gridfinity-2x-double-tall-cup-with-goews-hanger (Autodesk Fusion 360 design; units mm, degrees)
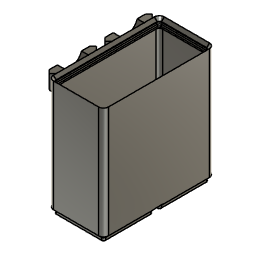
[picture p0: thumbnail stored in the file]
parameter "slotDimension" = 42
parameter "nestingDepth" = 5
parameter "nestingRimWidth" = 2.4
parameter "nestingClearance" = 0.25
parameter "cornerFillet" = 4
parameter "ledStripWidth" = 13
parameter "ledSlotHeight" = 4
parameter "screwTightDiameter" = 3
parameter "magnetDiameter" = 6.5
parameter "magnetThiccness" = 2.4
parameter "wallThiccness" = 1.2
sketch "Sketch1"
  line L1 (42, 42) -> (0, 42)
  line L2 (42, 0) -> (42, 42)
  line L3 (0, 0) -> (42, 0)
  line L4 (0, 42) -> (0, 0)
  line L5 (42, 0) -> (0, 42)
  line L6 (0, 21) -> (42, 21)
  line L7 (0, 14.5) -> (42, 14.5)
  line L8 (0, 27.5) -> (42, 27.5)
  line L9 (27.5, 0) -> (27.5, 42)
  line L10 (14.5, 0) -> (14.5, 42)
  line L11 (0, 0) -> (14.5, 14.5)
  circle C1 centre (8, 8) radius 1.5
  circle C2 centre (34, 8) radius 1.5
  circle C3 centre (34, 34) radius 1.5
  circle C4 centre (8, 34) radius 1.5
  circle C5 centre (8, 8) radius 3.25
  circle C6 centre (34, 8) radius 3.25
  circle C7 centre (34, 34) radius 3.25
  circle C8 centre (8, 34) radius 3.25
  point P1 (0, 0)
  point P6 (0, 0)
  point P5 (0, 0)
  point P7 (42, 21)
  point P8 (0, 21)
  point P9 (42, 14.5)
  point P10 (0, 14.5)
  point P11 (42, 27.5)
  point P12 (0, 27.5)
  point P13 (21, 21)
  point P18 (14.5, 14.5)
  point P19 (0, 0)
  point P20 (8, 8)
  point P4 (42, 0)
  point P3 (42, 42)
  point P24 (8, 8)
  horizontal L1
  perpendicular L1 L2
  parallel L1 L3
  parallel L2 L4
  coincident P1 P6
  coincident P1 P5
  midpoint L2 P7
  midpoint L4 P8
  coincident L2 P9
  coincident L4 P10
  perpendicular L4 L7
  symmetric L6 P9 P11
  symmetric L6 P10 P12
  midpoint L5 P13
  coincident L10 P18
  coincident L7 P18
  coincident P6 P19
  concentric C1 C5
  coincident L11 P20
  dimension "d1" distance P4 P5 = 42 (= "slotDimension")
  dimension "d2" distance P3 P4 = 42 (= "slotDimension")
  dimension "d65" distance L7 L8 = 13 (= "ledStripWidth")
  dimension "d69" diameter C1 = 3 (= "screwTightDiameter")
  dimension "d80" diameter C5 = 6.5 (= "magnetDiameter")
  dimension "d85" distance L3 P24 = 8
  dimension "d67" value = 90 (= "C-Pattern1-Angle")
  dimension "d71" value = 360 (= "C-Pattern2-Angle")
extrude "Extrude1" new body sketch "Sketch1" profile of L1 L2 L3 L4 blind 5 (= "nestingDepth")
work_plane "WorkPlane1" AlongDistance -21 (= "-slotDimension / 2")
sketch "Sketch2" plane through (0, 21, 0) normal (0, -1, 0) x axis (1, 0, 0)
  line L1 (0, 0) -> (42, 0)
  line L2 (0, 5) -> (0, 0)
  line L3 (2.4, 0.8) -> (3.2, 0)
  line L4 (0, 0) -> (3.2, 0)
  line L5 (2.4, 2.6) -> (2.4, 0.8)
  line L6 (0, 5) -> (2.4, 2.6)
  line L7 (-5.1222, 5) -> (0, 5)
  line L8 (-5.1222, -0.0937) -> (-5.1222, 5)
  line L9 (0, 0) -> (-5.1222, -0.0937)
  point P5 (3.2, 0)
  point P8 (0, 5)
  point P3 (0, 0)
  point P9 (0, 0)
  point P4 (0, 5)
  point P10 (0, 5)
  point P13 (0, 0)
  point P6 (2.4, 0.8)
  point P1 (0, 0)
  horizontal L4
  coincident L1 P5
  perpendicular L1 L5
  coincident L2 P8
  coincident P3 P9
  coincident P4 P10
  perpendicular L2 L7
  perpendicular L7 L8
  coincident P3 P13
  dimension "d39" angle L3 L4 = 45 (= "Angular Dimension-2")
  dimension "d40" angle L5 L6 = 45 (= "Angular Dimension-3")
  dimension "d41" distance P6 L4 = 0.8
  dimension "d43" distance L4 P8 = 5 (= "nestingDepth")
  dimension "d112" distance P1 P6 = 2.4 (= "nestingRimWidth")
sweep "Sweep1" sketch "Sketch2"
extrude "Extrude3" cut sketch "Sketch1" profile of L1 L2 L3 L4 L7 L8 L9 L10 blind 4 (= "ledSlotHeight")
draft "Draft1" "d74" 15 (= "Angle1") "d75" 0 (= "Angle2")
extrude "Extrude4" cut sketch "Sketch1" profile of C1 C2 C3 C4 to an object
extrude "Extrude5" cut sketch "Sketch1" profile of C1 C2 C3 C4 C5 C6 C7 C8 blind 2.4 (= "magnetThiccness")
rectangular_pattern "R-Pattern1" uSpaceDistance 42 (= "slotDimension") vSpaceDistance 42 (= "slotDimension")
sketch "Sketch4" plane through (0, 0, 5) normal (0, 0, 1) x axis (-1, 0, 0)
  line L1 (-38, 0) -> (-4, 0)
  line L2 (-42, -80) -> (-42, -4)
  line L3 (-4, -84) -> (-38, -84)
  line L4 (0, -4) -> (0, -80)
  line L5 (-4, -83.75) -> (-38, -83.75)
  line L6 (-0.25, -4) -> (-0.25, -80)
  line L7 (-38, -0.25) -> (-4, -0.25)
  line L8 (-41.75, -80) -> (-41.75, -4)
  arc A1 centre (-4, -4) radius 4 clockwise from (-4, 0) to (0, -4)
  arc A2 centre (-38, -4) radius 4 clockwise from (-42, -4) to (-38, 0)
  arc A3 centre (-38, -80) radius 4 clockwise from (-38, -84) to (-42, -80)
  arc A4 centre (-4, -80) radius 4 clockwise from (0, -80) to (-4, -84)
  arc A5 centre (-4, -80) radius 3.75 clockwise from (-0.25, -80) to (-4, -83.75)
  arc A6 centre (-4, -4) radius 3.75 clockwise from (-4, -0.25) to (-0.25, -4)
  arc A7 centre (-38, -4) radius 3.75 clockwise from (-41.75, -4) to (-38, -0.25)
  arc A8 centre (-38, -80) radius 3.75 clockwise from (-38, -83.75) to (-41.75, -80)
  point P1 (0, 0)
  point P2 (0, 0)
  point P3 (-42, 0)
  point P4 (0, -84)
  horizontal L1
  vertical L2
  horizontal L3
  vertical L4
  coincident P1 P2
  coincident P2 L1
  coincident P2 L4
  tangent L1 A1
  tangent L4 A1
  coincident P3 L1
  coincident P3 L2
  tangent L1 A2
  tangent L2 A2
  tangent L2 A3
  tangent L3 A3
  coincident P4 L3
  coincident P4 L4
  tangent L3 A4
  tangent L4 A4
  dimension "d44" distance P2 P3 = 42 (= "slotDimension * slotsWide")
  dimension "d45" distance P2 P4 = 84 (= "slotDimension * slotsDeep")
  dimension "d48" radius A1 = 4 (= "cornerFillet")
  dimension "d49" radius A2 = 4 (= "cornerFillet")
  dimension "d50" radius A3 = 4 (= "cornerFillet")
  dimension "d51" radius A4 = 4 (= "cornerFillet")
  dimension "d118" = -0.25
extrude "Extrude2" add sketch "Sketch4" along normal blind 79 (= "slotDimension * slotsHigh - nestingDepth")
sketch "Sketch5" plane through (21, 21, 2.5) normal (0, -1, 0) x axis (1, 0, 0)
  line L1 (-21, 2.5) -> (-18.6, 0.1)
  line L2 (-17, 2.5) -> (17, 2.5)
  line L3 (-18.6, 0.1) -> (-18.6, -1.7)
  line L4 (-18.6, -1.7) -> (-17.8, -2.5)
  line L5 (-21, 81.5) -> (-17, 81.5)
  line L6 (-21, 81.5) -> (-17, 81.5)
  line L7 (17, 81.5) -> (-17, 81.5)
  line L8 (17, 81.5) -> (21, 81.5)
  line L9 (17, 81.5) -> (21, 81.5)
  line L10 (-17, 81.5) -> (17, 81.5)
  line L11 (-21, 86.5) -> (-18.6, 84.1)
  line L12 (-18.6, 84.1) -> (-18.6, 82.3)
  line L13 (-18.6, 82.3) -> (-17.8, 81.5)
  line L14 (-21, 81.5) -> (-21, 2.5)
  line L15 (-21, 2.5) -> (-21, 81.5)
  line L16 (-21, 81.5) -> (-17.8, 81.5)
  line L17 (-21, 81.5) -> (-21, 86.5)
  line L18 (-18.85, 82.1964) -> (13.5232, 49.8232)
  line L19 (-18.85, 83.9964) -> (-18.85, 82.1964)
  line L20 (10.3232, 54.8232) -> (-18.85, 83.9964)
  point P22 (-21, 81.5)
  coincident L15 P22
  perpendicular L15 L16
  dimension "d54" R-Pattern1-uDistance = 0
  dimension "d55" R-Pattern1-vDistance = 84 (= "slotDimension * slotsHigh")
sweep "Sweep2" sketch "Sketch5"
extrude "Extrude2" cut sketch "Sketch4"
fillet "Fillet2" radius 0.6
extrude "Extrude1" cut of existing geometry
sketch "Sketch1 (1)" plane through (21, 21, 2.5) normal (0, -1, 0) x axis (1, 0, 0)
  line L1 (-18.1536, 81.5) -> (-18.1536, 3.7)
  line L2 (-18.1536, 3.7) -> (-18.1536, 81.5)
  line L3 (-19.55, 78.9036) -> (-18.1536, 80.3)
  line L4 (-20.3097, 80.3) -> (-18.1536, 80.3)
  line L5 (-19.55, 3.7) -> (-19.55, 78.9036)
  line L6 (-19.55, 3.7) -> (-18.1536, 3.7)
  line L7 (-20.75, 2.25) -> (-20.75, 86.25)
  line L8 (-20.75, 86.25) -> (-20.75, 2.25)
  line L9 (-20.75, 2.25) -> (-20.75, 2.5)
  line L10 (-20.75, 2.5) -> (-20.75, 2.25)
  point P4 (-18.1536, 80.3)
  point P2 (-18.1536, 3.7)
  point P8 (-18.1536, 3.7)
  point P7 (-19.55, 3.7)
  point P9 (-19.55, 3.7)
  point P3 (-18.1536, 81.5)
  horizontal L4
  coincident L1 P4
  parallel L2 L5
  coincident P2 P8
  perpendicular L2 L6
  coincident P7 P9
  dimension "d103" angle L3 L4 = 45 (= "Angular Dimension-2")
  dimension "d104" distance L5 L7 = 1.2 (= "wallThiccness")
  dimension "d105" distance P3 P4 = 1.2 (= "wallThiccness")
sweep "Sweep1" sketch "Sketch1 (1)"
combine "Combine2"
